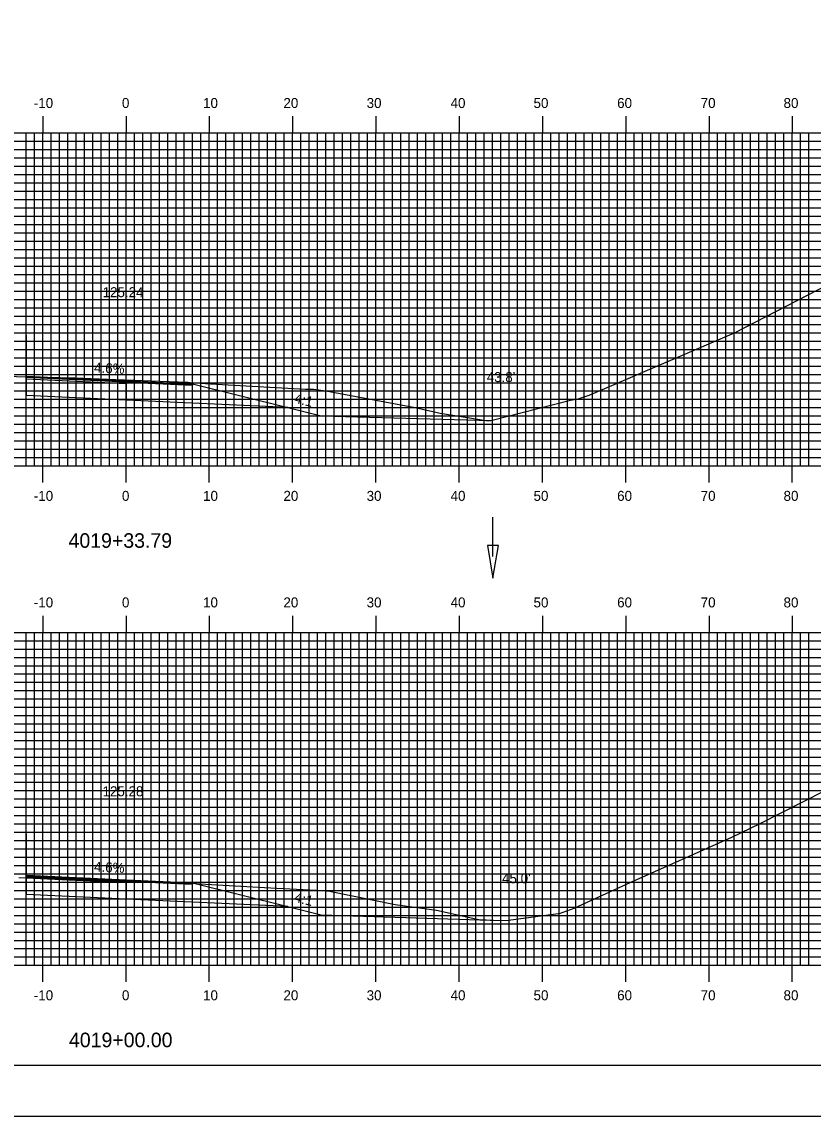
# Model space of a CAD drawing. Extents: x 854902 to 855245, y 364661 to 364881.
# Drawn here: x 855054.8 to 855149.8, y 364661.3 to 364792.7 of the extents above; entities that cross this region are included whole.
import ezdxf

# ---------------------------------------------------------------- set-up
doc = ezdxf.new("R2010")
doc.units = 0
for name, color, linetype in [('ANNOTATION', 7, 'Continuous'), ('BORDER', 7, 'Continuous'), ('D_Drainage_Ditch_Line', 7, 'Continuous'), ('D_Roadway_Centerline_Text', 7, 'Continuous'), ('D_Roadway_Edge_Shoulder', 7, 'Continuous'), ('D_Roadway_Edge_TW', 7, 'Continuous'), ('D_Roadway_Pavement', 7, 'Continuous'), ('D_Roadway_SubGrade', 7, 'Continuous'), ('D_Text_Standard', 7, 'Continuous'), ('H_V ANNOTATION', 7, 'Continuous'), ('M_Roadway_Centerline', 7, 'Continuous'), ('MAJOR', 7, 'Continuous'), ('MINOR', 7, 'Continuous'), ('PLOT BOUNDARY', 7, 'Continuous'), ('S_Roadway_Centerline', 7, 'Continuous')]:
    doc.layers.add(name, color=color, linetype=linetype)

msp = doc.modelspace()

# ---------------------------------------------------------------- linework, layer by layer
at = {"layer": 'ANNOTATION'}
for points in [[(855086.78, 364746.39), (855090.78, 364745.39)], [(855086.78, 364686.43), (855090.78, 364685.43), (855112.34, 364684.75)]]:
    msp.add_lwpolyline(points, dxfattribs=at)
at = {"layer": 'BORDER'}
msp.add_lwpolyline([(854917.75, 364667.37), (855237.75, 364667.37), (855237.75, 364877.37), (854917.75, 364877.37)], close=True, dxfattribs=at)
at = {"layer": 'D_Drainage_Ditch_Line'}
msp.add_line((855111.4, 364728.5), (855111.4, 364733.2), dxfattribs=at)
msp.add_lwpolyline([(855112.06, 364729.81), (855110.74, 364729.81), (855111.4, 364725.88)], close=True, dxfattribs=at)
at = {"layer": 'D_Roadway_Edge_Shoulder'}
for points in [[(855067.35, 364749.61), (855075.35, 364749.24), (855075.35, 364749.08), (855067.35, 364749.45)], [(855067.35, 364689.65), (855075.35, 364689.28), (855075.35, 364689.12), (855067.35, 364689.49)]]:
    msp.add_lwpolyline(points, close=True, dxfattribs=at)
at = {"layer": 'D_Roadway_Edge_TW'}
for points in [[(855055.35, 364750.16), (855067.35, 364749.61), (855067.35, 364749.45), (855055.35, 364750)], [(855055.35, 364690.2), (855067.35, 364689.65), (855067.35, 364689.49), (855055.35, 364690.04)]]:
    msp.add_lwpolyline(points, close=True, dxfattribs=at)
at = {"layer": 'D_Roadway_Pavement'}
for points in [[(855055.35, 364749.94), (855055.35, 364749.77)], [(855067.35, 364749.45), (855067.35, 364749.28)], [(855067.35, 364749.45), (855067.35, 364749.28)], [(855055.35, 364690.04), (855055.35, 364689.87)], [(855067.35, 364689.49), (855067.35, 364689.32)], [(855067.35, 364689.49), (855067.35, 364689.32)]]:
    msp.add_lwpolyline(points, dxfattribs=at)
msp.add_lwpolyline([(855055.35, 364690.04), (855067.35, 364689.49), (855067.35, 364689.32), (855055.35, 364689.87)], close=True, dxfattribs=at)
at = {"layer": 'D_Roadway_SubGrade'}
for p, q in [((855055.35, 364755.07), (855055.35, 364747.83)), ((855090.78, 364745.39), (855111.15, 364744.83)), ((855055.35, 364695.16), (855055.35, 364687.87))]:
    msp.add_line(p, q, dxfattribs=at)
for points in [[(855055.35, 364749.83), (855067.35, 364749.28), (855067.35, 364747.28), (855055.35, 364747.83)], [(855067.35, 364749.28), (855067.35, 364749.45), (855075.35, 364749.08), (855075.35, 364749.24), (855086.78, 364746.39), (855067.35, 364747.28)], [(855055.35, 364689.87), (855067.35, 364689.32), (855067.35, 364687.32), (855055.35, 364687.87)], [(855067.35, 364689.32), (855067.35, 364689.49), (855075.35, 364689.12), (855075.35, 364689.28), (855086.78, 364686.43), (855067.35, 364687.32)]]:
    msp.add_lwpolyline(points, close=True, dxfattribs=at)
at = {"layer": 'MAJOR'}
for p, q in [((855057.35, 364781.37), (855057.35, 364779.37)), ((855067.35, 364781.37), (855067.35, 364779.37)), ((855077.35, 364781.37), (855077.35, 364779.37)), ((855087.35, 364781.37), (855087.35, 364779.37)), ((855097.35, 364781.37), (855097.35, 364779.37)), ((855107.35, 364781.37), (855107.35, 364779.37)), ((855117.35, 364781.37), (855117.35, 364779.37)), ((855127.35, 364781.37), (855127.35, 364779.37)), ((855137.35, 364781.37), (855137.35, 364779.37)), ((855147.35, 364781.37), (855147.35, 364779.37)), ((854927.35, 364779.37), (855207.35, 364779.37)), ((854927.35, 364779.37), (855207.35, 364779.37)), ((855057.35, 364739.37), (855057.35, 364779.37)), ((855067.35, 364739.37), (855067.35, 364779.37)), ((855077.35, 364739.37), (855077.35, 364779.37)), ((855087.35, 364739.37), (855087.35, 364779.37)), ((855097.35, 364739.37), (855097.35, 364779.37)), ((855107.35, 364739.37), (855107.35, 364779.37)), ((855117.35, 364739.37), (855117.35, 364779.37)), ((855127.35, 364739.37), (855127.35, 364779.37)), ((855137.35, 364739.37), (855137.35, 364779.37)), ((855147.35, 364739.37), (855147.35, 364779.37)), ((854927.35, 364774.37), (855207.35, 364774.37)), ((854927.35, 364769.37), (855207.35, 364769.37)), ((854927.35, 364764.37), (855207.35, 364764.37)), ((854927.35, 364759.37), (855207.35, 364759.37)), ((854927.35, 364754.37), (855207.35, 364754.37)), ((854927.35, 364749.37), (855207.35, 364749.37)), ((854927.35, 364744.37), (855207.35, 364744.37)), ((854927.35, 364739.37), (855207.35, 364739.37)), ((854927.35, 364739.37), (855207.35, 364739.37)), ((855057.35, 364737.37), (855057.35, 364739.37)), ((855067.35, 364737.37), (855067.35, 364739.37)), ((855077.35, 364737.37), (855077.35, 364739.37)), ((855087.35, 364737.37), (855087.35, 364739.37)), ((855097.35, 364737.37), (855097.35, 364739.37)), ((855107.35, 364737.37), (855107.35, 364739.37)), ((855117.35, 364737.37), (855117.35, 364739.37)), ((855127.35, 364737.37), (855127.35, 364739.37)), ((855137.35, 364737.37), (855137.35, 364739.37)), ((855147.35, 364737.37), (855147.35, 364739.37)), ((855057.35, 364721.37), (855057.35, 364719.37)), ((855067.35, 364721.37), (855067.35, 364719.37)), ((855077.35, 364721.37), (855077.35, 364719.37)), ((855087.35, 364721.37), (855087.35, 364719.37)), ((855097.35, 364721.37), (855097.35, 364719.37)), ((855107.35, 364721.37), (855107.35, 364719.37)), ((855117.35, 364721.37), (855117.35, 364719.37)), ((855127.35, 364721.37), (855127.35, 364719.37)), ((855137.35, 364721.37), (855137.35, 364719.37)), ((855147.35, 364721.37), (855147.35, 364719.37)), ((854927.35, 364719.37), (855207.35, 364719.37)), ((854927.35, 364719.37), (855207.35, 364719.37)), ((855057.35, 364679.37), (855057.35, 364719.37)), ((855067.35, 364679.37), (855067.35, 364719.37)), ((855077.35, 364679.37), (855077.35, 364719.37)), ((855087.35, 364679.37), (855087.35, 364719.37)), ((855097.35, 364679.37), (855097.35, 364719.37)), ((855107.35, 364679.37), (855107.35, 364719.37)), ((855117.35, 364679.37), (855117.35, 364719.37)), ((855127.35, 364679.37), (855127.35, 364719.37)), ((855137.35, 364679.37), (855137.35, 364719.37)), ((855147.35, 364679.37), (855147.35, 364719.37)), ((854927.35, 364714.37), (855207.35, 364714.37)), ((854927.35, 364709.37), (855207.35, 364709.37)), ((854927.35, 364704.37), (855207.35, 364704.37)), ((854927.35, 364699.37), (855207.35, 364699.37)), ((854927.35, 364694.37), (855207.35, 364694.37)), ((854927.35, 364689.37), (855207.35, 364689.37)), ((854927.35, 364684.37), (855207.35, 364684.37)), ((854927.35, 364679.37), (855207.35, 364679.37)), ((854927.35, 364679.37), (855207.35, 364679.37)), ((855057.35, 364677.37), (855057.35, 364679.37)), ((855067.35, 364677.37), (855067.35, 364679.37)), ((855077.35, 364677.37), (855077.35, 364679.37)), ((855087.35, 364677.37), (855087.35, 364679.37)), ((855097.35, 364677.37), (855097.35, 364679.37)), ((855107.35, 364677.37), (855107.35, 364679.37)), ((855117.35, 364677.37), (855117.35, 364679.37)), ((855127.35, 364677.37), (855127.35, 364679.37)), ((855137.35, 364677.37), (855137.35, 364679.37)), ((855147.35, 364677.37), (855147.35, 364679.37))]:
    msp.add_line(p, q, dxfattribs=at)
at = {"layer": 'MINOR'}
for p, q in [((855055.35, 364739.37), (855055.35, 364779.37)), ((855056.35, 364739.37), (855056.35, 364779.37)), ((855058.35, 364739.37), (855058.35, 364779.37)), ((855059.35, 364739.37), (855059.35, 364779.37)), ((855060.35, 364739.37), (855060.35, 364779.37)), ((855061.35, 364739.37), (855061.35, 364779.37)), ((855062.35, 364739.37), (855062.35, 364779.37)), ((855063.35, 364739.37), (855063.35, 364779.37)), ((855064.35, 364739.37), (855064.35, 364779.37)), ((855065.35, 364739.37), (855065.35, 364779.37)), ((855066.35, 364739.37), (855066.35, 364779.37)), ((855068.35, 364739.37), (855068.35, 364779.37)), ((855069.35, 364739.37), (855069.35, 364779.37)), ((855070.35, 364739.37), (855070.35, 364779.37)), ((855071.35, 364739.37), (855071.35, 364779.37)), ((855072.35, 364739.37), (855072.35, 364779.37)), ((855073.35, 364739.37), (855073.35, 364779.37)), ((855074.35, 364739.37), (855074.35, 364779.37)), ((855075.35, 364739.37), (855075.35, 364779.37)), ((855076.35, 364739.37), (855076.35, 364779.37)), ((855078.35, 364739.37), (855078.35, 364779.37)), ((855079.35, 364739.37), (855079.35, 364779.37)), ((855080.35, 364739.37), (855080.35, 364779.37)), ((855081.35, 364739.37), (855081.35, 364779.37)), ((855082.35, 364739.37), (855082.35, 364779.37)), ((855083.35, 364739.37), (855083.35, 364779.37)), ((855084.35, 364739.37), (855084.35, 364779.37)), ((855085.35, 364739.37), (855085.35, 364779.37)), ((855086.35, 364739.37), (855086.35, 364779.37)), ((855088.35, 364739.37), (855088.35, 364779.37)), ((855089.35, 364739.37), (855089.35, 364779.37)), ((855090.35, 364739.37), (855090.35, 364779.37)), ((855091.35, 364739.37), (855091.35, 364779.37)), ((855092.35, 364739.37), (855092.35, 364779.37)), ((855093.35, 364739.37), (855093.35, 364779.37)), ((855094.35, 364739.37), (855094.35, 364779.37)), ((855095.35, 364739.37), (855095.35, 364779.37)), ((855096.35, 364739.37), (855096.35, 364779.37)), ((855098.35, 364739.37), (855098.35, 364779.37)), ((855099.35, 364739.37), (855099.35, 364779.37)), ((855100.35, 364739.37), (855100.35, 364779.37)), ((855101.35, 364739.37), (855101.35, 364779.37)), ((855102.35, 364739.37), (855102.35, 364779.37)), ((855103.35, 364739.37), (855103.35, 364779.37)), ((855104.35, 364739.37), (855104.35, 364779.37)), ((855105.35, 364739.37), (855105.35, 364779.37)), ((855106.35, 364739.37), (855106.35, 364779.37)), ((855108.35, 364739.37), (855108.35, 364779.37)), ((855109.35, 364739.37), (855109.35, 364779.37)), ((855110.35, 364739.37), (855110.35, 364779.37)), ((855111.35, 364739.37), (855111.35, 364779.37)), ((855112.35, 364739.37), (855112.35, 364779.37)), ((855113.35, 364739.37), (855113.35, 364779.37)), ((855114.35, 364739.37), (855114.35, 364779.37)), ((855115.35, 364739.37), (855115.35, 364779.37)), ((855116.35, 364739.37), (855116.35, 364779.37)), ((855118.35, 364739.37), (855118.35, 364779.37)), ((855119.35, 364739.37), (855119.35, 364779.37)), ((855120.35, 364739.37), (855120.35, 364779.37)), ((855121.35, 364739.37), (855121.35, 364779.37)), ((855122.35, 364739.37), (855122.35, 364779.37)), ((855123.35, 364739.37), (855123.35, 364779.37)), ((855124.35, 364739.37), (855124.35, 364779.37)), ((855125.35, 364739.37), (855125.35, 364779.37)), ((855126.35, 364739.37), (855126.35, 364779.37)), ((855128.35, 364739.37), (855128.35, 364779.37)), ((855129.35, 364739.37), (855129.35, 364779.37)), ((855130.35, 364739.37), (855130.35, 364779.37)), ((855131.35, 364739.37), (855131.35, 364779.37)), ((855132.35, 364739.37), (855132.35, 364779.37)), ((855133.35, 364739.37), (855133.35, 364779.37)), ((855134.35, 364739.37), (855134.35, 364779.37)), ((855135.35, 364739.37), (855135.35, 364779.37)), ((855136.35, 364739.37), (855136.35, 364779.37)), ((855138.35, 364739.37), (855138.35, 364779.37)), ((855139.35, 364739.37), (855139.35, 364779.37)), ((855140.35, 364739.37), (855140.35, 364779.37)), ((855141.35, 364739.37), (855141.35, 364779.37)), ((855142.35, 364739.37), (855142.35, 364779.37)), ((855143.35, 364739.37), (855143.35, 364779.37)), ((855144.35, 364739.37), (855144.35, 364779.37)), ((855145.35, 364739.37), (855145.35, 364779.37)), ((855146.35, 364739.37), (855146.35, 364779.37)), ((855148.35, 364739.37), (855148.35, 364779.37)), ((855149.35, 364739.37), (855149.35, 364779.37)), ((854927.35, 364778.37), (855207.35, 364778.37)), ((854927.35, 364777.37), (855207.35, 364777.37)), ((854927.35, 364776.37), (855207.35, 364776.37)), ((854927.35, 364775.37), (855207.35, 364775.37)), ((854927.35, 364773.37), (855207.35, 364773.37)), ((854927.35, 364772.37), (855207.35, 364772.37)), ((854927.35, 364771.37), (855207.35, 364771.37)), ((854927.35, 364770.37), (855207.35, 364770.37)), ((854927.35, 364768.37), (855207.35, 364768.37)), ((854927.35, 364767.37), (855207.35, 364767.37)), ((854927.35, 364766.37), (855207.35, 364766.37)), ((854927.35, 364765.37), (855207.35, 364765.37)), ((854927.35, 364763.37), (855207.35, 364763.37)), ((854927.35, 364762.37), (855207.35, 364762.37)), ((854927.35, 364761.37), (855207.35, 364761.37)), ((854927.35, 364760.37), (855207.35, 364760.37)), ((854927.35, 364758.37), (855207.35, 364758.37)), ((854927.35, 364757.37), (855207.35, 364757.37)), ((854927.35, 364756.37), (855207.35, 364756.37)), ((854927.35, 364755.37), (855207.35, 364755.37)), ((854927.35, 364753.37), (855207.35, 364753.37)), ((854927.35, 364752.37), (855207.35, 364752.37)), ((854927.35, 364751.37), (855207.35, 364751.37)), ((854927.35, 364750.37), (855207.35, 364750.37)), ((854927.35, 364748.37), (855207.35, 364748.37)), ((854927.35, 364747.37), (855207.35, 364747.37)), ((854927.35, 364746.37), (855207.35, 364746.37)), ((854927.35, 364745.37), (855207.35, 364745.37)), ((854927.35, 364743.37), (855207.35, 364743.37)), ((854927.35, 364742.37), (855207.35, 364742.37)), ((854927.35, 364741.37), (855207.35, 364741.37)), ((854927.35, 364740.37), (855207.35, 364740.37)), ((854927.35, 364718.37), (855207.35, 364718.37)), ((855055.35, 364679.37), (855055.35, 364719.37)), ((855056.35, 364679.37), (855056.35, 364719.37)), ((855058.35, 364679.37), (855058.35, 364719.37)), ((855059.35, 364679.37), (855059.35, 364719.37)), ((855060.35, 364679.37), (855060.35, 364719.37)), ((855061.35, 364679.37), (855061.35, 364719.37)), ((855062.35, 364679.37), (855062.35, 364719.37)), ((855063.35, 364679.37), (855063.35, 364719.37)), ((855064.35, 364679.37), (855064.35, 364719.37)), ((855065.35, 364679.37), (855065.35, 364719.37)), ((855066.35, 364679.37), (855066.35, 364719.37)), ((855068.35, 364679.37), (855068.35, 364719.37)), ((855069.35, 364679.37), (855069.35, 364719.37)), ((855070.35, 364679.37), (855070.35, 364719.37)), ((855071.35, 364679.37), (855071.35, 364719.37)), ((855072.35, 364679.37), (855072.35, 364719.37)), ((855073.35, 364679.37), (855073.35, 364719.37)), ((855074.35, 364679.37), (855074.35, 364719.37)), ((855075.35, 364679.37), (855075.35, 364719.37)), ((855076.35, 364679.37), (855076.35, 364719.37)), ((855078.35, 364679.37), (855078.35, 364719.37)), ((855079.35, 364679.37), (855079.35, 364719.37)), ((855080.35, 364679.37), (855080.35, 364719.37)), ((855081.35, 364679.37), (855081.35, 364719.37)), ((855082.35, 364679.37), (855082.35, 364719.37)), ((855083.35, 364679.37), (855083.35, 364719.37)), ((855084.35, 364679.37), (855084.35, 364719.37)), ((855085.35, 364679.37), (855085.35, 364719.37)), ((855086.35, 364679.37), (855086.35, 364719.37)), ((855088.35, 364679.37), (855088.35, 364719.37)), ((855089.35, 364679.37), (855089.35, 364719.37)), ((855090.35, 364679.37), (855090.35, 364719.37)), ((855091.35, 364679.37), (855091.35, 364719.37)), ((855092.35, 364679.37), (855092.35, 364719.37)), ((855093.35, 364679.37), (855093.35, 364719.37)), ((855094.35, 364679.37), (855094.35, 364719.37)), ((855095.35, 364679.37), (855095.35, 364719.37)), ((855096.35, 364679.37), (855096.35, 364719.37)), ((855098.35, 364679.37), (855098.35, 364719.37)), ((855099.35, 364679.37), (855099.35, 364719.37)), ((855100.35, 364679.37), (855100.35, 364719.37)), ((855101.35, 364679.37), (855101.35, 364719.37)), ((855102.35, 364679.37), (855102.35, 364719.37)), ((855103.35, 364679.37), (855103.35, 364719.37)), ((855104.35, 364679.37), (855104.35, 364719.37)), ((855105.35, 364679.37), (855105.35, 364719.37)), ((855106.35, 364679.37), (855106.35, 364719.37)), ((855108.35, 364679.37), (855108.35, 364719.37)), ((855109.35, 364679.37), (855109.35, 364719.37)), ((855110.35, 364679.37), (855110.35, 364719.37)), ((855111.35, 364679.37), (855111.35, 364719.37)), ((855112.35, 364679.37), (855112.35, 364719.37)), ((855113.35, 364679.37), (855113.35, 364719.37)), ((855114.35, 364679.37), (855114.35, 364719.37)), ((855115.35, 364679.37), (855115.35, 364719.37)), ((855116.35, 364679.37), (855116.35, 364719.37)), ((855118.35, 364679.37), (855118.35, 364719.37)), ((855119.35, 364679.37), (855119.35, 364719.37)), ((855120.35, 364679.37), (855120.35, 364719.37)), ((855121.35, 364679.37), (855121.35, 364719.37)), ((855122.35, 364679.37), (855122.35, 364719.37)), ((855123.35, 364679.37), (855123.35, 364719.37)), ((855124.35, 364679.37), (855124.35, 364719.37)), ((855125.35, 364679.37), (855125.35, 364719.37)), ((855126.35, 364679.37), (855126.35, 364719.37)), ((855128.35, 364679.37), (855128.35, 364719.37)), ((855129.35, 364679.37), (855129.35, 364719.37)), ((855130.35, 364679.37), (855130.35, 364719.37)), ((855131.35, 364679.37), (855131.35, 364719.37)), ((855132.35, 364679.37), (855132.35, 364719.37)), ((855133.35, 364679.37), (855133.35, 364719.37)), ((855134.35, 364679.37), (855134.35, 364719.37)), ((855135.35, 364679.37), (855135.35, 364719.37)), ((855136.35, 364679.37), (855136.35, 364719.37)), ((855138.35, 364679.37), (855138.35, 364719.37)), ((855139.35, 364679.37), (855139.35, 364719.37)), ((855140.35, 364679.37), (855140.35, 364719.37)), ((855141.35, 364679.37), (855141.35, 364719.37)), ((855142.35, 364679.37), (855142.35, 364719.37)), ((855143.35, 364679.37), (855143.35, 364719.37)), ((855144.35, 364679.37), (855144.35, 364719.37)), ((855145.35, 364679.37), (855145.35, 364719.37)), ((855146.35, 364679.37), (855146.35, 364719.37)), ((855148.35, 364679.37), (855148.35, 364719.37)), ((855149.35, 364679.37), (855149.35, 364719.37)), ((854927.35, 364717.37), (855207.35, 364717.37)), ((854927.35, 364716.37), (855207.35, 364716.37)), ((854927.35, 364715.37), (855207.35, 364715.37)), ((854927.35, 364713.37), (855207.35, 364713.37)), ((854927.35, 364712.37), (855207.35, 364712.37)), ((854927.35, 364711.37), (855207.35, 364711.37)), ((854927.35, 364710.37), (855207.35, 364710.37)), ((854927.35, 364708.37), (855207.35, 364708.37)), ((854927.35, 364707.37), (855207.35, 364707.37)), ((854927.35, 364706.37), (855207.35, 364706.37)), ((854927.35, 364705.37), (855207.35, 364705.37)), ((854927.35, 364703.37), (855207.35, 364703.37)), ((854927.35, 364702.37), (855207.35, 364702.37)), ((854927.35, 364701.37), (855207.35, 364701.37)), ((854927.35, 364700.37), (855207.35, 364700.37)), ((854927.35, 364698.37), (855207.35, 364698.37)), ((854927.35, 364697.37), (855207.35, 364697.37)), ((854927.35, 364696.37), (855207.35, 364696.37)), ((854927.35, 364695.37), (855207.35, 364695.37)), ((854927.35, 364693.37), (855207.35, 364693.37)), ((854927.35, 364692.37), (855207.35, 364692.37)), ((854927.35, 364691.37), (855207.35, 364691.37)), ((854927.35, 364690.37), (855207.35, 364690.37)), ((854927.35, 364688.37), (855207.35, 364688.37)), ((854927.35, 364687.37), (855207.35, 364687.37)), ((854927.35, 364686.37), (855207.35, 364686.37)), ((854927.35, 364685.37), (855207.35, 364685.37)), ((854927.35, 364683.37), (855207.35, 364683.37)), ((854927.35, 364682.37), (855207.35, 364682.37)), ((854927.35, 364681.37), (855207.35, 364681.37)), ((854927.35, 364680.37), (855207.35, 364680.37))]:
    msp.add_line(p, q, dxfattribs=at)
at = {"layer": 'PLOT BOUNDARY'}
msp.add_lwpolyline([(854901.56, 364661.25), (855241.56, 364661.25), (855241.56, 364881.25), (854901.56, 364881.25)], close=True, dxfattribs=at)
at = {"layer": 'S_Roadway_Centerline'}
for points in [[(855052.42, 364750.16), (855061.2, 364749.94), (855066.08, 364749.77), (855074.69, 364749.42), (855074.8, 364749.42), (855075.06, 364749.4), (855077.49, 364749.25), (855088.88, 364748.6), (855089.87, 364748.59), (855091.34, 364748.4), (855102.06, 364746.37), (855105.05, 364745.7), (855110.59, 364744.84), (855111.15, 364744.83), (855120.72, 364747.26), (855121.65, 364747.41), (855122.96, 364747.86), (855125.41, 364748.92), (855140.39, 364755.35), (855158.02, 364764.44)], [(855054.48, 364689.93), (855065.13, 364689.56), (855072.67, 364689.32), (855075.55, 364689.22), (855076.23, 364689.16), (855077.6, 364689.06), (855083.96, 364688.72), (855085.46, 364688.64), (855090.99, 364688.35), (855091.78, 364688.28), (855099.67, 364686.67), (855104.63, 364685.99), (855109.7, 364684.89), (855112.34, 364684.75), (855113.27, 364684.81), (855119.24, 364685.61), (855119.4, 364685.59), (855121.15, 364686.23), (855127.87, 364689.33), (855140.09, 364694.78), (855143.49, 364696.42), (855148.79, 364699.11), (855158.78, 364704.18)]]:
    msp.add_lwpolyline(points, dxfattribs=at)

# ---------------------------------------------------------------- texts
at = {"layer": 'ANNOTATION'}
for s, rotation, p in [('4.6%', 357.3663, (855063.49, 364750.59)), ('4:1', 345.9638, (855087.47, 364746.98)), ('4.6%', 357.3663, (855063.49, 364690.63)), ('4:1', 345.9638, (855087.47, 364687.02))]:
    msp.add_text(s, height=1.2, rotation=rotation, dxfattribs=at).set_placement(p)
at = {"layer": 'D_Roadway_Centerline_Text'}
for s, p in [('125.24', (855064.54, 364759.64)), ('125.28', (855064.53, 364699.68))]:
    msp.add_text(s, height=1.2, dxfattribs=at).set_placement(p)
at = {"layer": 'D_Text_Standard'}
for s, p in [("43.8'", (855110.66, 364749.44)), ("45.0'", (855112.5, 364689.22))]:
    msp.add_text(s, height=1.2, dxfattribs=at).set_placement(p)
at = {"layer": 'H_V ANNOTATION'}
for s, height, p in [('-10', 1.2, (855056.28, 364782.37)), ('0', 1.2, (855066.86, 364782.37)), ('10', 1.2, (855076.6, 364782.37)), ('20', 1.2, (855086.25, 364782.37)), ('30', 1.2, (855096.24, 364782.37)), ('40', 1.2, (855106.32, 364782.37)), ('50', 1.2, (855116.28, 364782.37)), ('60', 1.2, (855126.32, 364782.37)), ('70', 1.2, (855136.35, 364782.37)), ('80', 1.2, (855146.3, 364782.37)), ('-10', 1.2, (855056.28, 364735.17)), ('0', 1.2, (855066.86, 364735.17)), ('10', 1.2, (855076.6, 364735.17)), ('20', 1.2, (855086.25, 364735.17)), ('30', 1.2, (855096.24, 364735.17)), ('40', 1.2, (855106.32, 364735.17)), ('50', 1.2, (855116.28, 364735.17)), ('60', 1.2, (855126.32, 364735.17)), ('70', 1.2, (855136.35, 364735.17)), ('80', 1.2, (855146.3, 364735.17)), ('4019+33.79', 1.75, (855060.45, 364729.53)), ('-10', 1.2, (855056.28, 364722.37)), ('0', 1.2, (855066.86, 364722.37)), ('10', 1.2, (855076.6, 364722.37)), ('20', 1.2, (855086.25, 364722.37)), ('30', 1.2, (855096.24, 364722.37)), ('40', 1.2, (855106.32, 364722.37)), ('50', 1.2, (855116.28, 364722.37)), ('60', 1.2, (855126.32, 364722.37)), ('70', 1.2, (855136.35, 364722.37)), ('80', 1.2, (855146.3, 364722.37)), ('-10', 1.2, (855056.28, 364675.17)), ('0', 1.2, (855066.86, 364675.17)), ('10', 1.2, (855076.6, 364675.17)), ('20', 1.2, (855086.25, 364675.17)), ('30', 1.2, (855096.24, 364675.17)), ('40', 1.2, (855106.32, 364675.17)), ('50', 1.2, (855116.28, 364675.17)), ('60', 1.2, (855126.32, 364675.17)), ('70', 1.2, (855136.35, 364675.17)), ('80', 1.2, (855146.3, 364675.17)), ('4019+00.00', 1.75, (855060.5, 364669.53))]:
    msp.add_text(s, height=height, dxfattribs=at).set_placement(p)
at = {"layer": 'M_Roadway_Centerline'}
for s, p in [('C', (855074.8, 364749.42)), ('L', (855074.8, 364749.41)), ('C', (855075.55, 364689.22)), ('L', (855075.55, 364689.22))]:
    msp.add_text(s, height=0.0146, dxfattribs=at).set_placement(p)

doc.saveas('drawing.dxf')
